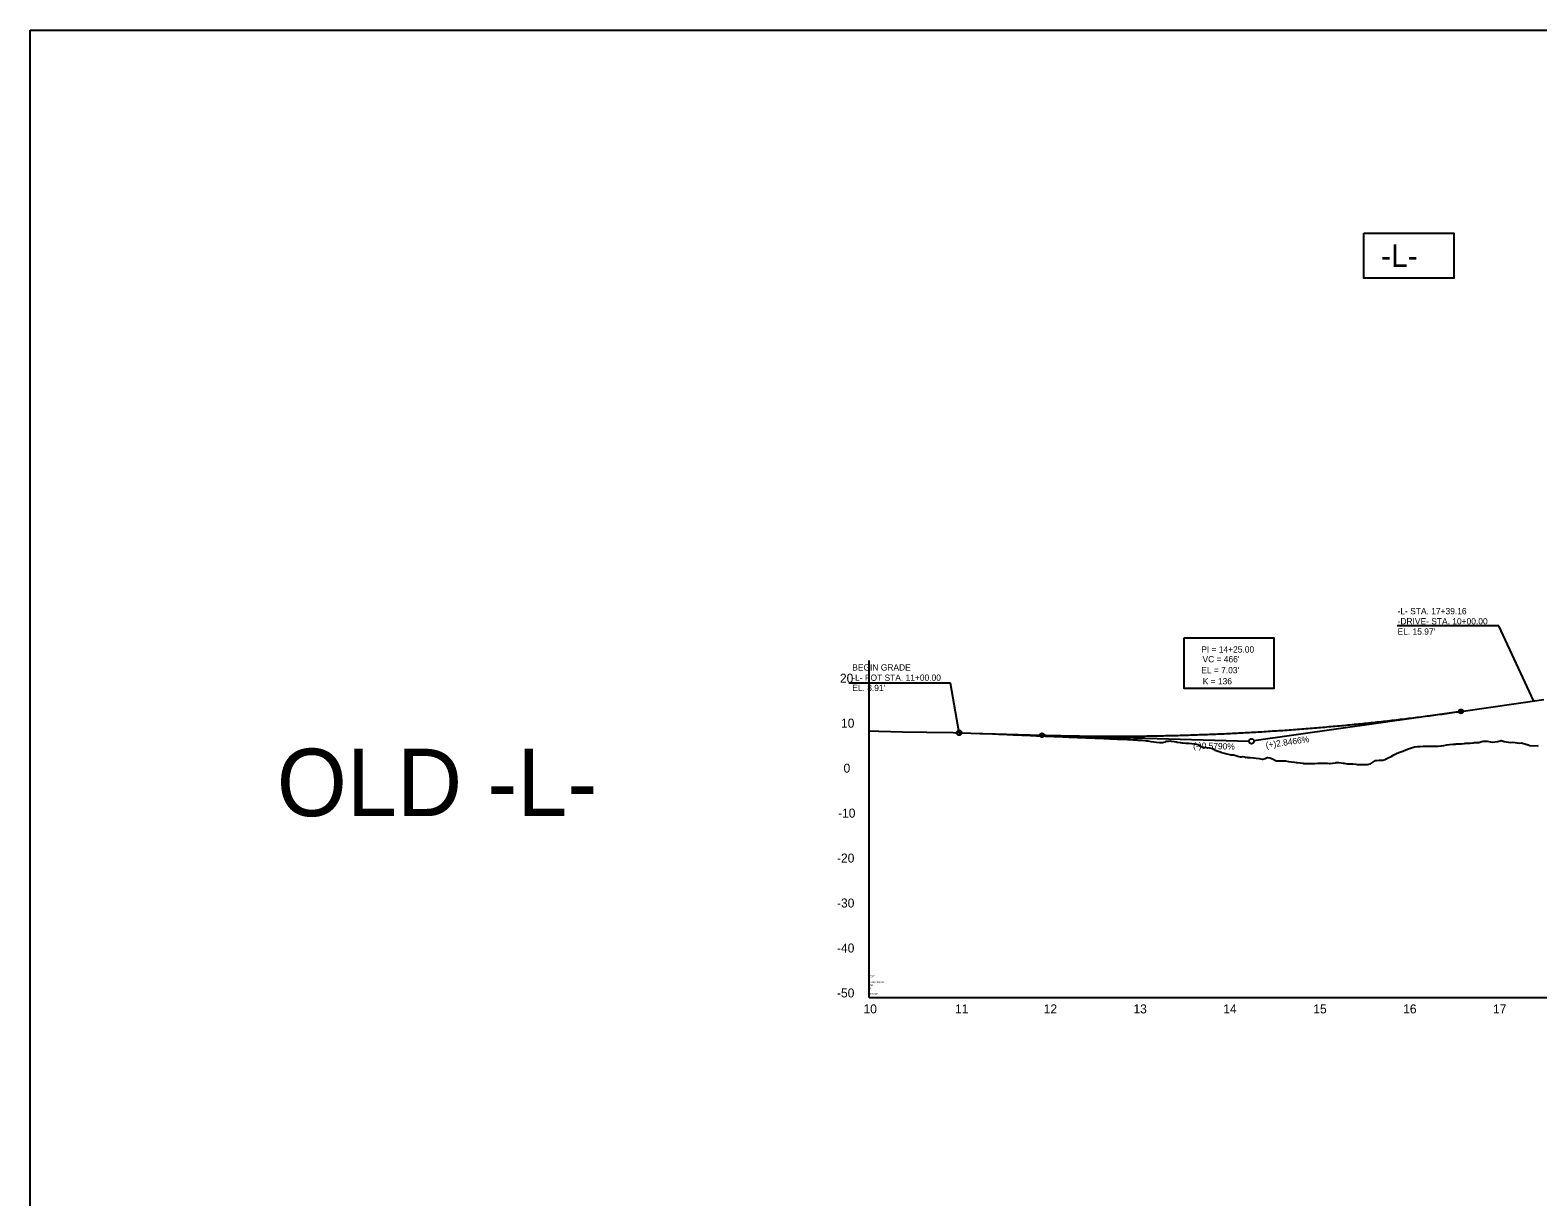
# Model space of a CAD drawing. Extents: x 1626634 to 1638383, y 876896 to 886347.
# Drawn here: x 1626634 to 1628311, y 879589 to 880886 of the extents above; entities that cross this region are included whole.
import ezdxf

# ---------------------------------------------------------------- set-up
doc = ezdxf.new("R2010")
doc.units = 0
for name, color, linetype in [('Exist Profile Cell', 7, 'Continuous'), ('Exist Vertical Profile Ground Line', 7, 'Continuous'), ('Exist Vertical Profile Horizontal Axis Label Major', 7, 'Continuous'), ('Exist Vertical Profile Vertical Axis Label', 7, 'Continuous'), ('Prop Vertical Profile Curve Label', 7, 'Continuous'), ('Prop Vertical Profile Grade', 7, 'Continuous'), ('Prop Vertical Profile Grade Label', 7, 'Continuous'), ('Prop VPI Label', 7, 'Continuous')]:
    doc.layers.add(name, color=color, linetype=linetype)

msp = doc.modelspace()

# ---------------------------------------------------------------- linework, layer by layer
at = {"layer": 'Exist Profile Cell'}
for q in [(1627567.6, 880185.5), (1629802.7, 879810.5), (1627567.6, 879810.5)]:
    msp.add_line((1627567.6, 879810.5), q, dxfattribs=at)
at = {"layer": 'Exist Vertical Profile Ground Line'}
msp.add_lwpolyline([(1627567.6, 880107.1), (1627577.8, 880106.8), (1627578.3, 880106.8), (1627604.6, 880106.2), (1627631.2, 880105.8), (1627631.5, 880105.8), (1627661, 880105.2), (1627690.5, 880104.4), (1627704.7, 880103.8), (1627707.9, 880103.7), (1627711.2, 880103.6), (1627714.5, 880103.5), (1627716.8, 880103.4), (1627717.7, 880103.3), (1627721, 880103.2), (1627724.2, 880103.1), (1627727.5, 880102.9), (1627730.7, 880102.8), (1627734, 880102.7), (1627737.3, 880102.5), (1627740.5, 880102.4), (1627741.9, 880102.3), (1627743.8, 880102.2), (1627747, 880102.1), (1627750.3, 880102), (1627753.6, 880101.8), (1627756.8, 880101.7), (1627760.1, 880101.5), (1627763.3, 880101.4), (1627766.6, 880101.3), (1627768.7, 880101.2), (1627769.8, 880101.1), (1627773.1, 880101), (1627773.5, 880101), (1627776.4, 880100.9), (1627779.6, 880100.7), (1627782.9, 880100.6), (1627786.1, 880100.4), (1627789.4, 880100.3), (1627792.7, 880100.2), (1627794.6, 880100.1), (1627795.9, 880100), (1627799.2, 880099.9), (1627802.4, 880099.8), (1627804.2, 880099.7), (1627805.7, 880099.6), (1627808.9, 880099.5), (1627812.2, 880099.4), (1627815.5, 880099.3), (1627818.7, 880099.1), (1627822, 880099), (1627825.2, 880098.9), (1627828.5, 880098.7), (1627831.8, 880098.6), (1627835.2, 880098.4), (1627838.3, 880098.3), (1627841.5, 880098.2), (1627843.2, 880098.1), (1627844.8, 880098.1), (1627848, 880097.9), (1627851.3, 880097.8), (1627854.6, 880097.6), (1627857.8, 880097.5), (1627861.1, 880097.3), (1627864.3, 880097.2), (1627865.7, 880097.1), (1627866.5, 880096.8), (1627867.8, 880096.9), (1627869.1, 880096.9), (1627869.8, 880096.9), (1627870.2, 880096.8), (1627871, 880096.7), (1627874.1, 880096.3), (1627876, 880096.1), (1627877.4, 880095.9), (1627880.6, 880095.5), (1627883.9, 880095.1), (1627887.1, 880094.7), (1627890.4, 880094.3), (1627891.5, 880094.1), (1627893.7, 880094.3), (1627895.3, 880094.4), (1627896.9, 880095.1), (1627897.9, 880095.6), (1627900.2, 880095.7), (1627902.9, 880095.9), (1627903.4, 880095.8), (1627906.7, 880095.3), (1627908.8, 880094.9), (1627910, 880094.7), (1627913.2, 880094.2), (1627915.3, 880093.9), (1627916.5, 880093.8), (1627919.7, 880093.6), (1627922.2, 880093.5), (1627923, 880093.4), (1627926.2, 880093.1), (1627929.5, 880092.7), (1627931.6, 880092.5), (1627932.8, 880091.9), (1627936, 880090.2), (1627938.5, 880089), (1627939.3, 880088.9), (1627942.5, 880088.5), (1627946.1, 880088.1), (1627949.3, 880087.4), (1627951.7, 880086), (1627952.3, 880085.8), (1627955.6, 880084.5), (1627958.8, 880083.3), (1627959.3, 880083.1), (1627960.6, 880082.7), (1627962.1, 880082.3), (1627965.3, 880081.5), (1627968.6, 880080.8), (1627969.5, 880080.6), (1627971.9, 880080.5), (1627972.7, 880080.4), (1627975.1, 880079.7), (1627978.4, 880078.8), (1627980.2, 880078.2), (1627980.9, 880078.1), (1627981.6, 880078.3), (1627983, 880078.7), (1627984.9, 880078.1), (1627986, 880077.7), (1627987.7, 880077.8), (1627988.2, 880077.7), (1627991.4, 880077.4), (1627994.7, 880077.1), (1627997.9, 880076.8), (1628001.2, 880076.4), (1628004.4, 880075.8), (1628005.4, 880075.5), (1628007.7, 880076.6), (1628009.9, 880077.6), (1628011, 880077.5), (1628013.2, 880077.3), (1628014.2, 880076.8), (1628017.5, 880075.2), (1628020, 880073.9), (1628020.7, 880073.9), (1628024, 880073.9), (1628027.3, 880073.9), (1628028.6, 880073.9), (1628030.1, 880073.9), (1628030.5, 880073.8), (1628033.8, 880073.2), (1628037, 880072.7), (1628040.3, 880072.2), (1628042.4, 880071.9), (1628043.5, 880071.8), (1628046.8, 880071.5), (1628050.2, 880071.2), (1628051, 880071), (1628053.3, 880071), (1628056.6, 880070.9), (1628059.8, 880070.9), (1628060.2, 880070.9), (1628062.1, 880070.8), (1628063.1, 880070.9), (1628066.4, 880071.1), (1628069.6, 880071.3), (1628070.3, 880071.4), (1628072.9, 880071.3), (1628076.1, 880071.2), (1628077.2, 880071.2), (1628079.4, 880070.8), (1628080.3, 880070.7), (1628082.6, 880071.1), (1628085.9, 880071.7), (1628086.6, 880071.8), (1628089.2, 880072), (1628090.3, 880072.1), (1628092.4, 880071.7), (1628094.5, 880071.4), (1628095.7, 880071.2), (1628098.9, 880070.6), (1628100.3, 880070.4), (1628102.2, 880070.4), (1628105.5, 880070.4), (1628108.7, 880070.1), (1628110.3, 880069.9), (1628112, 880069.9), (1628115.2, 880069.9), (1628115.7, 880069.9), (1628118.5, 880069.8), (1628120.3, 880069.7), (1628121.7, 880069.9), (1628124.6, 880070.4), (1628125, 880070.6), (1628128.3, 880072.8), (1628130.4, 880074.2), (1628131.5, 880074.3), (1628134.8, 880074.6), (1628135.7, 880074.7), (1628138, 880074.7), (1628138.8, 880074.6), (1628141.3, 880075.4), (1628141.7, 880075.6), (1628144.6, 880077.1), (1628147.8, 880078.8), (1628151.1, 880080.6), (1628154, 880082), (1628154.3, 880082.3), (1628154.8, 880082.5), (1628157.6, 880083.5), (1628160.8, 880084.7), (1628164.1, 880085.9), (1628167.4, 880087.1), (1628170.6, 880088.3), (1628173.9, 880089.4), (1628177.1, 880089.6), (1628180.4, 880089.8), (1628183.7, 880090), (1628186.9, 880090.1), (1628190.4, 880090.2), (1628193.4, 880090.1), (1628197, 880090), (1628200, 880090.3), (1628200.4, 880090.3), (1628203.2, 880090.4), (1628203.9, 880090.4), (1628206.5, 880091), (1628209.7, 880091.7), (1628210.4, 880091.8), (1628213, 880092), (1628216.5, 880092.2), (1628219.5, 880092.5), (1628220.4, 880092.6), (1628222.8, 880092.7), (1628226.2, 880092.8), (1628229.3, 880093.2), (1628230.4, 880093.4), (1628232.5, 880093.4), (1628235.8, 880093.3), (1628239.1, 880094), (1628240.4, 880094.3), (1628242.3, 880094.2), (1628245.6, 880094.2), (1628248.8, 880095.3), (1628250.4, 880095.8), (1628252.1, 880095.8), (1628254.8, 880095.7), (1628260.4, 880094.4), (1628266.7, 880095.2), (1628270.4, 880096.4), (1628273.8, 880095.2), (1628280.5, 880094.3), (1628283.3, 880094.5), (1628290.5, 880093.6), (1628292.8, 880093.7), (1628300.5, 880091.8), (1628302.2, 880090.9), (1628310.5, 880090.4), (1628311.7, 880091)], dxfattribs=at)
at = {"layer": 'Prop Vertical Profile Curve Label'}
msp.add_lwpolyline([(1626634.5, 880886.3), (1630394.5, 880886.3), (1630394.5, 878291.7), (1626634.5, 878291.7)], close=True, dxfattribs=at)
for centre in [(1628225.6, 880128.8), (1627759.6, 880102.3)]:
    msp.add_circle(centre, 2.25, dxfattribs=at)
at = {"layer": 'Prop Vertical Profile Grade'}
for p, q in [((1628225.6, 880128.8), (1628317.6, 880141.9)), ((1627667.6, 880105), (1627759.6, 880102.3))]:
    msp.add_line(p, q, dxfattribs=at)
msp.add_spline([(1627759.6, 880102.3), (1627768.9, 880102.1), (1627778.3, 880101.9), (1627787.6, 880101.7), (1627796.9, 880101.5), (1627806.2, 880101.4), (1627815.5, 880101.3), (1627824.9, 880101.2), (1627834.2, 880101.2), (1627843.5, 880101.2), (1627852.8, 880101.2), (1627862.1, 880101.3), (1627871.5, 880101.4), (1627880.8, 880101.5), (1627890.1, 880101.7), (1627899.4, 880101.9), (1627908.7, 880102.1), (1627918.1, 880102.4), (1627927.4, 880102.7), (1627936.7, 880103), (1627946, 880103.3), (1627955.3, 880103.7), (1627964.7, 880104.1), (1627974, 880104.6), (1627983.3, 880105.1), (1627992.6, 880105.6), (1628001.9, 880106.1), (1628011.3, 880106.7), (1628020.6, 880107.3), (1628029.9, 880107.9), (1628039.2, 880108.6), (1628048.5, 880109.3), (1628057.9, 880110.1), (1628067.2, 880110.8), (1628076.5, 880111.6), (1628085.8, 880112.5), (1628095.1, 880113.3), (1628104.5, 880114.2), (1628113.8, 880115.1), (1628123.1, 880116.1), (1628132.4, 880117.1), (1628141.7, 880118.1), (1628151.1, 880119.2), (1628160.4, 880120.3), (1628169.7, 880121.4), (1628179, 880122.5), (1628188.3, 880123.7), (1628197.7, 880124.9), (1628207, 880126.2), (1628216.3, 880127.5), (1628225.6, 880128.8)], degree=3, dxfattribs=at)
at = {"layer": 'Prop VPI Label'}
for p, q in [((1628267.8, 880223.9), (1628154.6, 880223.9)), ((1628306.8, 880140.3), (1628267.8, 880223.9)), ((1627657.9, 880160.3), (1627544.8, 880160.3)), ((1627667.6, 880105), (1627657.9, 880160.3)), ((1628225.6, 880128.8), (1627995.3, 880096)), ((1627759.6, 880102.3), (1627989.9, 880095.7))]:
    msp.add_line(p, q, dxfattribs=at)
for points in [[(1628117.6, 880660.5), (1628217.6, 880660.5), (1628217.6, 880610.5), (1628117.6, 880610.5)], [(1628117.6, 880660.5), (1628217.6, 880660.5), (1628217.6, 880610.5), (1628117.6, 880610.5)], [(1628117.6, 880660.5), (1628217.6, 880660.5), (1628217.6, 880610.5), (1628117.6, 880610.5)], [(1628117.6, 880660.5), (1628217.6, 880660.5), (1628217.6, 880610.5), (1628117.6, 880610.5)], [(1627917.6, 880210.5), (1628017.6, 880210.5), (1628017.6, 880154.3), (1627917.6, 880154.3)], [(1627917.6, 880210.5), (1628017.6, 880210.5), (1628017.6, 880154.3), (1627917.6, 880154.3)]]:
    msp.add_lwpolyline(points, close=True, dxfattribs=at)
for centre in [(1627667.6, 880105), (1627667.6, 880105), (1627667.6, 880105), (1627992.6, 880095.6)]:
    msp.add_circle(centre, 2.75, dxfattribs=at)

# ---------------------------------------------------------------- texts
at = {"layer": 'Exist Profile Cell'}
for s, p in [('RDY', (1627567.6, 879833.2)), ('L', (1627567.6, 879830)), ('-50', (1627567.6, 879823.5)), ('5', (1627567.6, 879820.2)), ('1000.000000', (1627567.6, 879826.7)), ('1', (1627567.6, 879817)), ('NOGAP', (1627567.6, 879813.7))]:
    msp.add_text(s, height=2, dxfattribs=at).set_placement(p)
at = {"layer": 'Exist Vertical Profile Horizontal Axis Label Major'}
for s, p in [('10', (1627561.2, 879793)), ('11', (1627663, 879793)), ('12', (1627761.6, 879793)), ('13', (1627861.4, 879793)), ('14', (1627961.3, 879793)), ('15', (1628061.4, 879793)), ('16', (1628161.3, 879793)), ('17', (1628261.2, 879793))]:
    msp.add_text(s, height=10, dxfattribs=at).set_placement(p)
at = {"layer": 'Exist Vertical Profile Vertical Axis Label'}
for s, p in [('20', (1627535, 880160.7)), ('10', (1627536.2, 880110.7)), ('0', (1627539, 880060.7)), ('-10', (1627532.9, 880010.7)), ('-20', (1627531.7, 879960.7)), ('-30', (1627531.7, 879910.7)), ('-40', (1627531.7, 879860.7)), ('-50', (1627531.7, 879810.7))]:
    msp.add_text(s, height=10, dxfattribs=at).set_placement(p)
at = {"layer": 'Prop Vertical Profile Curve Label'}
for s, height, p in [('-L-', 25, (1628136.7, 880623)), ("VC = 466'", 7, (1627938.2, 880183.4)), ('K = 136', 7, (1627938.4, 880158.8)), ('OLD -L-', 75, (1626908.7, 880012.3))]:
    msp.add_text(s, height=height, dxfattribs=at).set_placement(p)
at = {"layer": 'Prop Vertical Profile Grade Label'}
for s, rotation, p in [('(+)2.8466%', 8.1004, (1628009, 880087.8)), ('(-)0.5790%', 358.3417, (1627927.7, 880087.5))]:
    msp.add_text(s, height=7, rotation=rotation, dxfattribs=at).set_placement(p)
at = {"layer": 'Prop VPI Label'}
for s, p in [('-L- STA. 17+39.16', (1628155.1, 880236.8)), ('-DRIVE- STA. 10+00.00', (1628155.1, 880225.5)), ("EL. 15.97'", (1628155.1, 880214.1)), ('PI = 14+25.00', (1627936.8, 880194.2)), ('-L- POT STA. 11+00.00', (1627548.7, 880162.8)), ('BEGIN GRADE', (1627548.7, 880174.2)), ("EL = 7.03'", (1627936.8, 880171.2)), ("EL. 8.91'", (1627548.7, 880151.5))]:
    msp.add_text(s, height=7, dxfattribs=at).set_placement(p)

doc.saveas('drawing.dxf')
